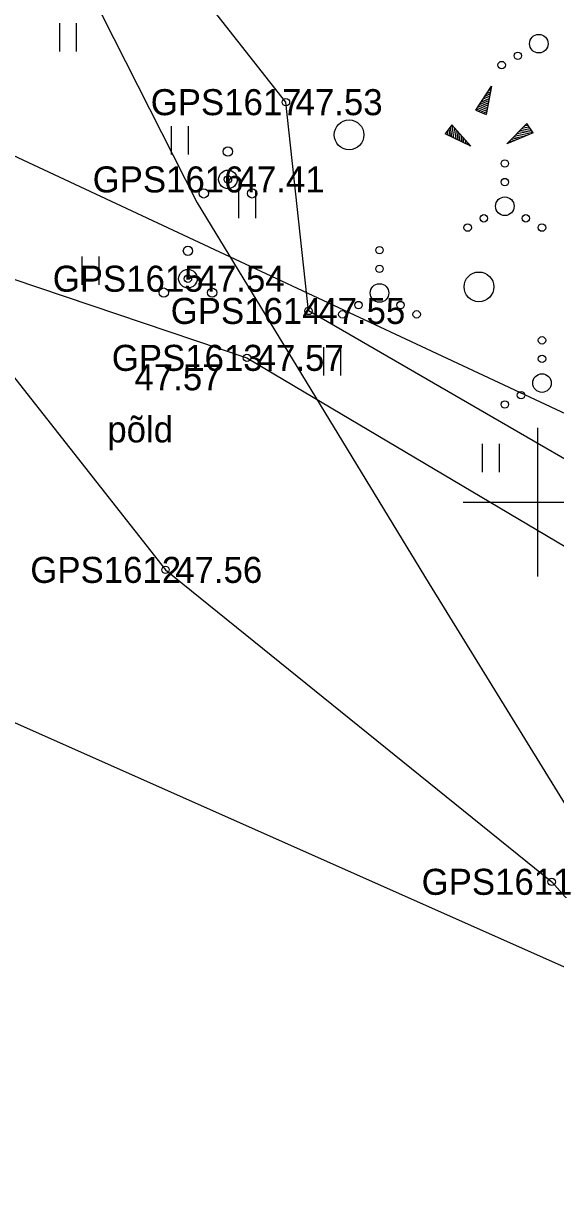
# Model space of a CAD drawing. Extents: x 551623 to 559850, y 6561220 to 6567135.
# Drawn here: x 555036.16 to 555050.49, y 6565581.59 to 6565612.88 of the extents above; entities that cross this region are included whole.
import ezdxf

# ---------------------------------------------------------------- set-up
doc = ezdxf.new("R2010")
doc.units = 0
for name, color, linetype in [('DTRASS', 7, 'Continuous'), ('HALJASTUS', 7, 'Continuous'), ('KORGUS-EH2000', 7, 'Continuous'), ('KPKAABEL', 7, 'Continuous'), ('MOOTKORG-EH2000', 7, 'Continuous'), ('MOOTMPUNKT', 7, 'Continuous'), ('MOOTNR', 7, 'Continuous'), ('MOOTPIIR', 7, 'Continuous'), ('PUU', 7, 'Continuous'), ('RELJEEF', 7, 'Continuous'), ('VORK', 7, 'Continuous')]:
    doc.layers.add(name, color=color, linetype=linetype)

msp = doc.modelspace()

# ---------------------------------------------------------------- linework, layer by layer
at = {"layer": 'DTRASS'}
for p, q in [((555055.061, 6565600.359), (555006.518, 6565623.049)), ((555063.371, 6565581.881), (555027.329, 6565597.89))]:
    msp.add_line(p, q, dxfattribs=at)
at = {"layer": 'HALJASTUS'}
for p, q in [((555037.132, 6565612.883), (555037.132, 6565612.122)), ((555037.587, 6565612.883), (555037.587, 6565612.122)), ((555040.145, 6565610.116), (555040.145, 6565609.355)), ((555040.6, 6565610.116), (555040.6, 6565609.355)), ((555041.957, 6565608.406), (555041.957, 6565607.645)), ((555042.412, 6565608.406), (555042.412, 6565607.645)), ((555037.737, 6565606.607), (555037.737, 6565605.846)), ((555038.192, 6565606.607), (555038.192, 6565605.846)), ((555044.239, 6565604.173), (555044.239, 6565603.412)), ((555044.694, 6565604.173), (555044.694, 6565603.412)), ((555048.509, 6565601.572), (555048.509, 6565600.811)), ((555048.964, 6565601.572), (555048.964, 6565600.811))]:
    msp.add_line(p, q, dxfattribs=at)
for points in [[(555057.023, 6565609.855), (555058.586, 6565605.616), (555058.613, 6565599.497), (555057.015, 6565597.532), (555043.839, 6565605.146), (555043.23, 6565610.761), (555037.198, 6565618.427), (555042.201, 6565623.493), (555040.415, 6565628.763), (555044.392, 6565634.613), (555048.032, 6565636.033)], [(555033.078, 6565606.955), (555042.182, 6565603.884), (555055.024, 6565596.272), (555056.694, 6565594.201), (555060.942, 6565588.507), (555062.867, 6565584.513)]]:
    msp.add_lwpolyline(points, dxfattribs=at)
for centre, radius in [((555050.035, 6565612.334), 0.25), ((555049.47, 6565612.009), 0.1), ((555049.035, 6565611.759), 0.1), ((555044.928, 6565609.882), 0.4), ((555049.12, 6565609.112), 0.1), ((555049.12, 6565608.612), 0.1), ((555049.12, 6565607.962), 0.25), ((555048.555, 6565607.637), 0.1), ((555049.685, 6565607.637), 0.1), ((555048.12, 6565607.387), 0.1), ((555050.12, 6565607.387), 0.1), ((555045.748, 6565606.779), 0.1), ((555045.748, 6565606.279), 0.1), ((555048.425, 6565605.793), 0.4), ((555045.748, 6565605.629), 0.25), ((555044.748, 6565605.054), 0.1), ((555045.183, 6565605.304), 0.1), ((555046.313, 6565605.304), 0.1), ((555046.748, 6565605.054), 0.1), ((555050.122, 6565604.356), 0.1), ((555050.122, 6565603.856), 0.1), ((555050.122, 6565603.206), 0.25), ((555049.557, 6565602.881), 0.1), ((555049.122, 6565602.631), 0.1)]:
    msp.add_circle(centre, radius, dxfattribs=at)
at = {"layer": 'KORGUS-EH2000'}
for centre in [(555043.23, 6565610.761), (555043.839, 6565605.146), (555042.182, 6565603.884), (555039.99, 6565598.181), (555050.382, 6565589.791)]:
    msp.add_circle(centre, 0.1, dxfattribs=at)
at = {"layer": 'KPKAABEL'}
msp.add_lwpolyline([(555016.436, 6565669.854), (555020.596, 6565667.742), (555021.693, 6565667.12), (555022.688, 6565666.158), (555023.697, 6565665.37), (555024.08, 6565664.769), (555021.622, 6565652.627), (555021.526, 6565649.765), (555022.786, 6565647.231), (555026.485, 6565641.465), (555030.606, 6565629.728), (555035.378, 6565618.813), (555040.844, 6565608.057), (555047.089, 6565597.805), (555053.567, 6565587.292), (555056.073, 6565583.696), (555062.108, 6565572.667), (555068.248, 6565560.982)], dxfattribs=at)
at = {"layer": 'MOOTMPUNKT'}
for centre in [(555043.23, 6565610.761), (555041.669, 6565608.683), (555040.593, 6565606.013), (555043.839, 6565605.146), (555042.182, 6565603.884), (555039.99, 6565598.181), (555050.382, 6565589.791)]:
    msp.add_circle(centre, 0.1, dxfattribs=at)
at = {"layer": 'MOOTPIIR'}
msp.add_lwpolyline([(555026.508, 6565625.245), (555032.663, 6565611.321), (555033.078, 6565606.955), (555039.99, 6565598.181), (555050.382, 6565589.791), (555055.753, 6565583.761), (555063.202, 6565573.546), (555069.448, 6565559.262)], dxfattribs=at)
at = {"layer": 'PUU'}
for centre, radius in [((555041.669, 6565609.433), 0.125), ((555041.669, 6565608.683), 0.25), ((555041.019, 6565608.308), 0.125), ((555042.319, 6565608.308), 0.125), ((555040.593, 6565606.763), 0.125), ((555040.593, 6565606.013), 0.25), ((555039.943, 6565605.638), 0.125), ((555041.243, 6565605.638), 0.125)]:
    msp.add_circle(centre, radius, dxfattribs=at)
at = {"layer": 'RELJEEF'}
for p, q in [((555048.34, 6565610.548), (555048.76, 6565611.188)), ((555048.76, 6565611.188), (555048.62, 6565610.433)), ((555048.685, 6565611.073), (555048.745, 6565611.098)), ((555048.735, 6565611.148), (555048.755, 6565611.158)), ((555048.39, 6565610.623), (555048.675, 6565610.743)), ((555048.44, 6565610.698), (555048.69, 6565610.803)), ((555048.49, 6565610.773), (555048.615, 6565610.828)), ((555048.54, 6565610.848), (555048.71, 6565610.923)), ((555048.59, 6565610.923), (555048.72, 6565610.983)), ((555048.615, 6565610.828), (555048.7, 6565610.863)), ((555048.635, 6565610.998), (555048.735, 6565611.038)), ((555048.34, 6565610.548), (555048.665, 6565610.688)), ((555048.34, 6565610.548), (555048.62, 6565610.433)), ((555048.34, 6565610.548), (555048.34, 6565610.548)), ((555048.405, 6565610.523), (555048.655, 6565610.628)), ((555048.47, 6565610.493), (555048.645, 6565610.568)), ((555048.54, 6565610.468), (555048.635, 6565610.508)), ((555048.605, 6565610.443), (555048.62, 6565610.448)), ((555047.698, 6565610.147), (555047.513, 6565609.907)), ((555047.698, 6565610.147), (555048.203, 6565609.577)), ((555047.698, 6565610.147), (555047.743, 6565609.797)), ((555047.698, 6565610.147), (555047.698, 6565610.147)), ((555049.177, 6565609.642), (555049.717, 6565610.187)), ((555049.767, 6565610.112), (555049.667, 6565610.132)), ((555049.727, 6565610.172), (555049.707, 6565610.172)), ((555049.887, 6565609.937), (555049.717, 6565610.187)), ((555048.203, 6565609.577), (555047.513, 6565609.907)), ((555047.523, 6565609.922), (555047.528, 6565609.902)), ((555047.568, 6565609.977), (555047.583, 6565609.877)), ((555047.613, 6565610.037), (555047.638, 6565609.852)), ((555047.653, 6565610.092), (555047.688, 6565609.822)), ((555047.758, 6565610.082), (555047.798, 6565609.772)), ((555047.818, 6565610.012), (555047.853, 6565609.747)), ((555047.878, 6565609.947), (555047.893, 6565609.807)), ((555047.893, 6565609.807), (555047.908, 6565609.717)), ((555047.933, 6565609.877), (555047.963, 6565609.692)), ((555047.993, 6565609.812), (555048.013, 6565609.667)), ((555049.887, 6565609.937), (555049.177, 6565609.642)), ((555049.552, 6565609.797), (555049.367, 6565609.832)), ((555049.502, 6565609.857), (555049.412, 6565609.877)), ((555049.717, 6565609.867), (555049.452, 6565609.917)), ((555049.802, 6565609.902), (555049.497, 6565609.962)), ((555049.637, 6565609.832), (555049.502, 6565609.857)), ((555049.887, 6565609.937), (555049.537, 6565610.002)), ((555049.847, 6565609.992), (555049.582, 6565610.047)), ((555049.807, 6565610.052), (555049.622, 6565610.087)), ((555049.887, 6565609.937), (555049.887, 6565609.937)), ((555048.053, 6565609.742), (555048.068, 6565609.642)), ((555048.113, 6565609.677), (555048.123, 6565609.612)), ((555048.173, 6565609.607), (555048.178, 6565609.587)), ((555049.217, 6565609.657), (555049.202, 6565609.662)), ((555049.302, 6565609.692), (555049.242, 6565609.707)), ((555049.387, 6565609.727), (555049.282, 6565609.747)), ((555049.467, 6565609.762), (555049.327, 6565609.792))]:
    msp.add_line(p, q, dxfattribs=at)
at = {"layer": 'VORK'}
for p, q in [((555050, 6565602), (555050, 6565598)), ((555048, 6565600), (555052, 6565600))]:
    msp.add_line(p, q, dxfattribs=at)

# ---------------------------------------------------------------- texts
at = {"layer": 'HALJASTUS'}
msp.add_text('põld', height=0.7, rotation=359.9544, dxfattribs=at).set_placement((555038.423, 6565601.611))
at = {"layer": 'KORGUS-EH2000'}
for s, p in [(' 47.53', (555043.23, 6565610.411)), (' 47.55', (555043.839, 6565604.796)), (' 47.57', (555038.894, 6565603.012)), (' 47.56', (555039.99, 6565597.831))]:
    msp.add_text(s, height=0.7, dxfattribs=at).set_placement(p)
at = {"layer": 'MOOTKORG-EH2000'}
for s, p in [(' 47.53', (555043.23, 6565610.411)), (' 47.41', (555041.669, 6565608.333)), (' 47.54', (555040.593, 6565605.663)), (' 47.55', (555043.839, 6565604.796)), (' 47.57', (555042.182, 6565603.534)), (' 47.56', (555039.99, 6565597.831))]:
    msp.add_text(s, height=0.7, dxfattribs=at).set_placement(p)
at = {"layer": 'MOOTNR'}
for s, p in [('GPS1617 ', (555039.591, 6565610.411)), ('GPS1616 ', (555038.029, 6565608.333)), ('GPS1615 ', (555036.954, 6565605.663)), ('GPS1614 ', (555040.129, 6565604.796)), ('GPS1613 ', (555038.543, 6565603.534)), ('GPS1612 ', (555036.35, 6565597.831)), ('GPS1611 ', (555046.882, 6565589.441))]:
    msp.add_text(s, height=0.7, dxfattribs=at).set_placement(p)

doc.saveas('drawing.dxf')
